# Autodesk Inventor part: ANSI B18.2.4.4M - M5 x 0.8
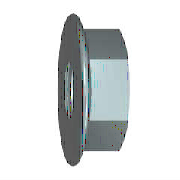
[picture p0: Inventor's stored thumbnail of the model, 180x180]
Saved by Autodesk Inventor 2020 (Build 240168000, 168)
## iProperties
IsCustomPart: 0
Created: 2008-02
Part Number: ANSI B18.2.4.4M - M5 x 0.8
Material: Steel, Mild
Description: Metric Hex Flange Nut
Document SubType Name: Modeling
Standard: ANSI B18.2.4.4M
Designer: PN
Standard Revision: 1999
Standards Organization: ANSI
Language: en-US
Size Designation: M5 x 0.8
Categories: <MemberInstance><Categories><Category DisplayName="Fasteners" InternalName="e4da775c-781d-43d5-af7c-5136215cf5a6" Mnemonic="FSTN"><Category DisplayName="Nuts" I
Density: 7.86 g/cm^3
Mass: 2.42166 g
Surface Area: 3.62968 cm^2
Volume: 0.308099 cm^3
Appearance: Steel
Author: PN
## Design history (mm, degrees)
sketch "Sketch1"
  geometry: L1 (-1.23, 0)-(6.038, 0) reference; L2 (2.674, 4)-(1.866, 5.4); L3 (2.674, 4)-(5, 4); L4 (5, 4)-(5, 0); L5 (2.674, 4)-(2.674, 0); L6 (0, -1.223)-(0, 7.339) reference; A1 r 1 centre (1, 4.9) between (1.866, 5.4) and (0, 4.9); 1 further point
  constraints: 8 end point, 3 point on line, 2 perpendicular, 2 point on circle, 2 tangent, 1 centre point, 1 parallel
  dimensions: "d2" = 8 diameter of L3 L1 (= SW); "d4" = 11.8 dimension on A1 L1 (= LADI); "d5" = 1 radius of A1 (= PHH); "d15" = 5 distance between parallel lines of L4 L6 (= KOH); "d16" = 30 deg angle of L6 L2 (= KEWI)
revolve "Ring" sketch "Sketch1" stored, may be unused: angle "d8" = 90 deg
sketch "Sketch2"
  geometry: L1 (-4, -2.309)-(-4, 2.309); L2 (-4, 2.309)-(0, 4.619); L3 (0, 4.619)-(4, 2.309); L4 (4, 2.309)-(4, -2.309); L5 (4, -2.309)-(0, -4.619); L6 (0, -4.619)-(-4, -2.309); C1 r 4.9 at (0, 0); C2 r 4.9 at (0, 0) reference; 1 further point
  constraints: 12 end point, 1 centre point, 1 coincident, 1 vertical, 11 other
  dimensions: "d6" = 9.2376 distance of L5.end L2.end (= 1.1547 x SW)
extrude "Body" join sketch "Sketch2" distance "d7" = 5 (= KOH); taper "d9" = 0 deg
sketch "Sketch3"
  geometry: L1 (2.317, 4.619)-(5, 4.619) reference; L2 (5, 2.309)-(5, 4.619) reference; L3 (0, -4.9)-(0, 4.9) reference; L4 (-1, 0)-(6, 0) reference; L5 (4.643, 4.619)-(5, 4)
  constraints: 2 end point, 2 point on line
  dimensions: "d10" = 30 deg angle of L2 L5 (= ANG1); "d11" = 8 diameter of L5.end L4 (= SW0)
revolve "Chamfer1" sketch "Sketch3" stored, may be unused: angle "d24" = 90 deg
sketch "Sketch4"
  geometry: C1 r 4.9 at (0, 0) reference; 1 further point
  constraints: 1 coincident
hole "Thread" sketch "Sketch4" at (0, 0) diameter "d25" = 4.134; stored, may be unused: countersink angle "d29" = 82 deg, drill point angle "d31" = 118 deg; dims "d26" = 6, "d27" = 4, "d28" = 2, "d30" = 8
workaxis "Work Axis1"
workplane "Work Plane1"
body "Solid1"
chamfer "Chamfer2" distance "d12" = 0.43301 (= -0.5 x GD1 + 0.5 x NND); stored, may be unused: angle "d13" = 30 deg, second distance "d46" = 0.43301 (= -0.5 x GD1 + 0.5 x NND)
chamfer "Chamfer3" distance "d51" = 0.43301 (= -0.5 x GD1 + 0.5 x NND); stored, may be unused: second distance "d52" = 2, angle "d53" = 45 deg
other parameters: "ANG1" = 30 deg [user parameter; used in 1 equation term], "KEWI" = 30 deg [user parameter; used in 1 equation term], "NND" = 5 [user parameter; used in 3 equation terms], "LADI" = 11.8 [user parameter; used in 2 equation terms], "SW" = 8 [user parameter; used in 4 equation terms], "PHH" = 1 (= RR) [user parameter; used in 2 equation terms], "KOH" = 5 [user parameter; used in 2 equation terms], "SW0" = 8 (= SW) [user parameter; used in 1 equation term], "GD1" = 4.13397 (computed from THREADDIA, PTC, TOA) [user parameter; used in 3 equation terms], "d1" = 11.8 (= LADI), "d3" = 1 (= PHH), "d45" = 0, "d47" = 0, "d49" = 0, "d54" = 0, "GUL" = 0.43301 (= 0.541266 x PTC) [user parameter], "TPU" = 12.5 (computed from PTC) [user parameter], "RR" = 1 [user parameter; used in 1 equation term], "THREADDIA" = 5 [user parameter; used in 1 equation term], "TOA" = 30 deg [user parameter; used in 1 equation term], "PTC" = 0.8 [user parameter; used in 4 equation terms], "RR1" = 0.3 [user parameter], "GAL" = 0.43301 (= 0.541266 x PTC) [user parameter], "E0" = 9.24 (= 1.155 x SW) [user parameter]
